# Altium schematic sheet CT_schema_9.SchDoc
size 308 x 195 mm
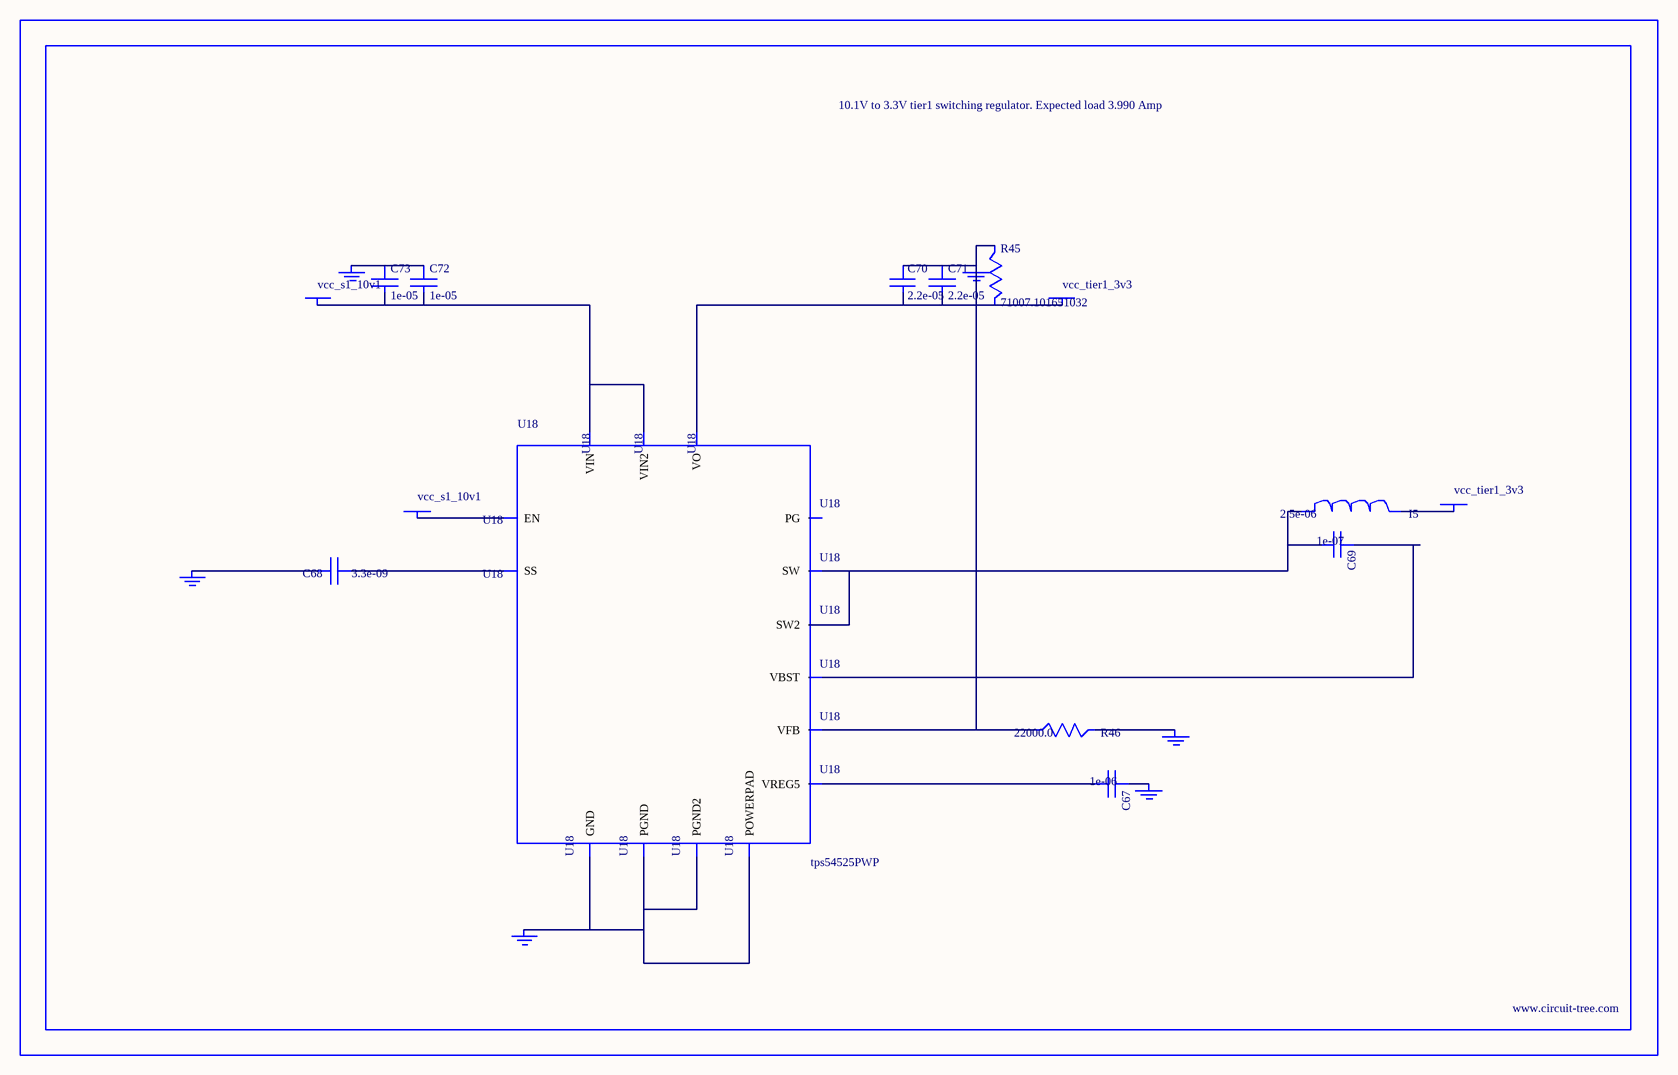
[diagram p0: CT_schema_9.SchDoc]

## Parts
BORDER8  (no value)
C67  1e-06  [C0603]
C68  3.3e-09  [C0402]
C69  1e-07  [C0402]
C70  2.2e-05  [C1210]
C71  2.2e-05  [C1210]
C72  1e-05  [C1206]
C73  1e-05  [C1206]
GND_INSTANCE_8_0  (no value)
GND_INSTANCE_8_1  (no value)
GND_INSTANCE_8_2  (no value)
GND_INSTANCE_8_3  (no value)
GND_INSTANCE_8_4  (no value)
GND_INSTANCE_8_5  (no value)
I5  2.5e-06  [DR1040]
POWER_INSTANCE_8_0  vcc_tier1_3v3
POWER_INSTANCE_8_1  vcc_s1_10v1
POWER_INSTANCE_8_2  vcc_tier1_3v3
POWER_INSTANCE_8_3  vcc_s1_10v1
R45  71007.101651032  [R0603]
R46  22000.0  [R0603]
U18  tps54525PWP  [HTSSOP14]

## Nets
NetC67_1: C67.1 GND_INSTANCE_8_2.0(GND)
NetC67_2: C67.2 U18.3(VREG5)
NetC68_1: C68.1 U18.4(SS)
NetC68_2: C68.2 GND_INSTANCE_8_3.0(GND)
NetC69_1: C69.1 U18.12(VBST)
NetC69_2: C69.2 I5.1 U18.10(SW) U18.11(SW2)
NetC70_1: C70.1 C71.1 GND_INSTANCE_8_0.0(GND) R45.1 R46.1 U18.2(VFB)
NetC70_2: C70.2 C71.2 POWER_INSTANCE_8_0.0(PWR) R45.2 U18.1(VO)
NetC72_1: C72.1 C73.1 GND_INSTANCE_8_5.0(GND)
NetC72_2: C72.2 C73.2 POWER_INSTANCE_8_3.0(PWR) U18.13(VIN) U18.14(VIN2)
NetGND_INSTANCE_8_1_0: GND_INSTANCE_8_1.0(GND) R46.2
NetGND_INSTANCE_8_4_0: GND_INSTANCE_8_4.0(GND) U18.5(GND) U18.8(PGND) U18.9(PGND2) U18.15(POWERPAD)
NetI5_2: I5.2 POWER_INSTANCE_8_2.0(PWR)
NetPOWER_INSTANCE_8_1_0: POWER_INSTANCE_8_1.0(PWR) U18.7(EN)

Not connected (* = marked no-connect by the designer): U18 6(PG)

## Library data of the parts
BORDER8 = BORDER_PAGE8
C67 = C0603C105K3RACTU
C68 = C0402C332K3RAC
C69 = C0402C104K3RACTU
C70 C71 = GRM32ER61E226ME15L
C72 C73 = C1206C106K3RACTU
GND_INSTANCE_8_0-GND_INSTANCE_8_5 = GND
I5 = DR1040-2R5-R
POWER_INSTANCE_8_0-POWER_INSTANCE_8_3 = PWR
R45 = R45
R46 = RC0603JR-0722KL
